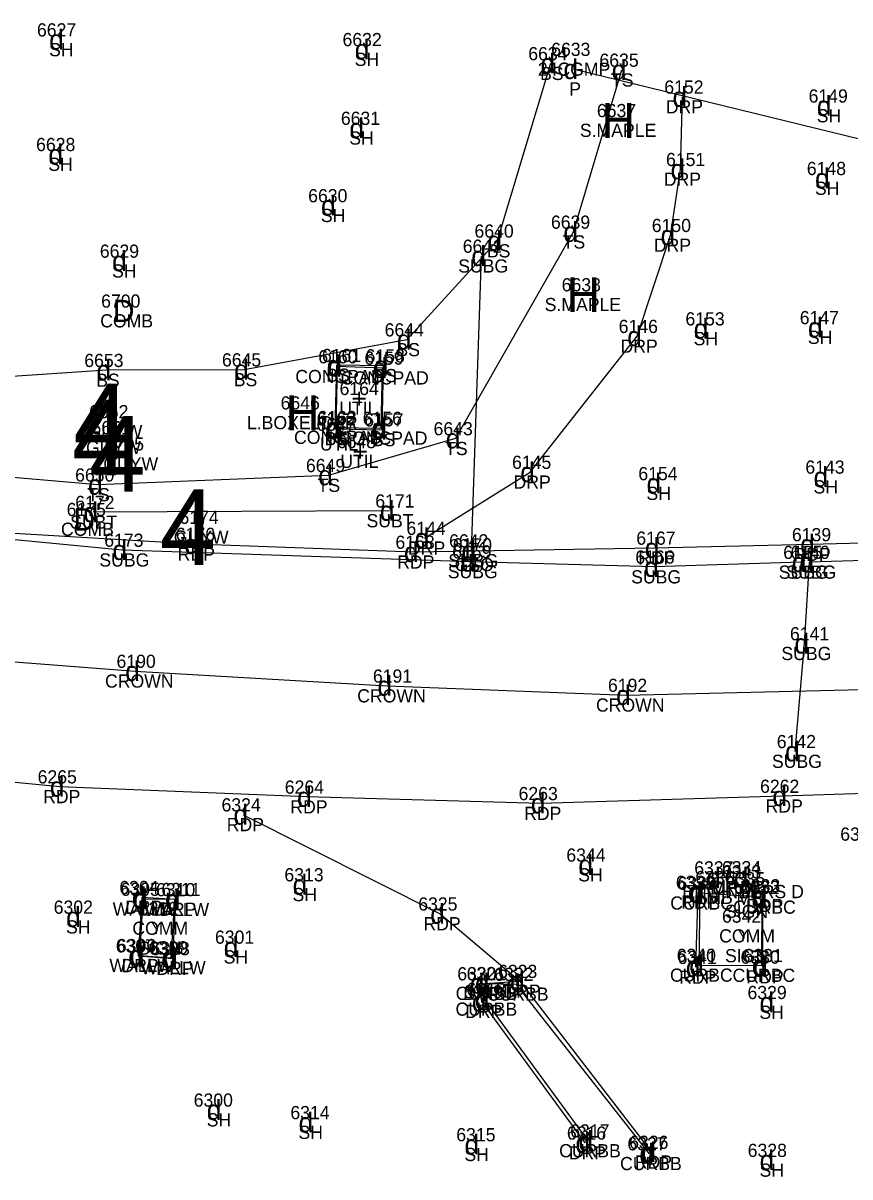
# Model space of a CAD drawing. Extents: x 69415 to 80913, y 7576 to 15059.
# Drawn here: x 75119.5 to 75244.9, y 14346.6 to 14521.7 of the extents above; entities that cross this region are included whole.
import ezdxf

# ---------------------------------------------------------------- set-up
doc = ezdxf.new("R2010")
doc.units = 0
for name, color, linetype in [('Level 11', 7, 'Continuous'), ('Level 12', 7, 'Continuous'), ('Level 14', 7, 'Continuous'), ('Level 15', 7, 'Continuous'), ('Level 43', 7, 'Continuous'), ('Level 46', 7, 'Continuous'), ('Level 47', 7, 'Continuous'), ('Level 48', 7, 'Continuous'), ('Level 59', 7, 'Continuous')]:
    doc.layers.add(name, color=color, linetype=linetype)

msp = doc.modelspace()

# ---------------------------------------------------------------- linework, layer by layer
at = {"layer": 'Level 11'}
for p, q in [((75219.21, 14499.48), (75219.51, 14510.47)), ((75217.7, 14489.47), (75219.21, 14499.48)), ((75212.64, 14474.15), (75217.7, 14489.47)), ((75196.41, 14453.54), (75212.64, 14474.15)), ((75180.39, 14443.53), (75196.41, 14453.54)), ((75145.45, 14442.61), (75114.29, 14444.48)), ((75285.14, 14443.84), (75238.88, 14442.56)), ((75178.76, 14441.41), (75145.45, 14442.61)), ((75215.3, 14442.03), (75178.76, 14441.41)), ((75238.88, 14442.56), (75215.3, 14442.03)), ((75125.04, 14405.82), (75089.24, 14409.2)), ((75162.54, 14404.26), (75125.04, 14405.82)), ((75273.17, 14405.59), (75234.65, 14404.39)), ((75198.01, 14403.28), (75162.54, 14404.26)), ((75234.65, 14404.39), (75198.01, 14403.28)), ((75152.89, 14401.57), (75182.75, 14386.53)), ((75224.62, 14392.01), (75221.83, 14389.82)), ((75228.82, 14392.04), (75224.62, 14392.01)), ((75231.7, 14389.29), (75228.82, 14392.04)), ((75221.83, 14389.82), (75221.52, 14378.43)), ((75222.09, 14389.68), (75222.05, 14378.74)), ((75231.63, 14389.05), (75222.09, 14389.68)), ((75231.73, 14378.47), (75231.7, 14389.29)), ((75137.48, 14389.03), (75136.93, 14380.18)), ((75142.64, 14388.73), (75137.48, 14389.03)), ((75142.21, 14379.76), (75142.64, 14388.73)), ((75231.54, 14378.71), (75231.63, 14389.05)), ((75182.75, 14386.53), (75194.86, 14376.3)), ((75136.93, 14380.18), (75142.21, 14379.76)), ((75222.05, 14378.74), (75231.54, 14378.71)), ((75188.75, 14375.94), (75194.86, 14376.3)), ((75189.07, 14373.23), (75188.75, 14375.94)), ((75189.51, 14373.58), (75189.52, 14375.97)), ((75189.52, 14375.97), (75194.26, 14375.86)), ((75194.26, 14375.86), (75214.47, 14350.15)), ((75194.86, 14376.3), (75214.81, 14350.38)), ((75205.23, 14352.1), (75189.51, 14373.58)), ((75204.78, 14351.78), (75189.07, 14373.23))]:
    msp.add_line(p, q, dxfattribs=at)
at = {"layer": 'Level 12'}
for p, q in [((75167.15, 14469.55), (75166.94, 14460.33)), ((75174.02, 14469.34), (75167.15, 14469.55)), ((75173.81, 14460.21), (75174.02, 14469.34)), ((75166.94, 14460.33), (75173.81, 14460.21)), ((75137.66, 14388.76), (75137.15, 14380.22)), ((75142.49, 14388.7), (75137.66, 14388.76)), ((75141.96, 14379.88), (75142.49, 14388.7)), ((75137.15, 14380.22), (75141.96, 14379.88))]:
    msp.add_line(p, q, dxfattribs=at)
at = {"layer": 'Level 15'}
for p, q in [((75188.98, 14486.32), (75187.48, 14441.62)), ((75175.1, 14447.67), (75130.14, 14447.45)), ((75134.54, 14441.72), (75093.04, 14445.68)), ((75187.39, 14439.95), (75134.54, 14441.72)), ((75215.21, 14439.16), (75187.39, 14439.95)), ((75237.59, 14439.87), (75215.21, 14439.16)), ((75238.75, 14439.88), (75238, 14427.53)), ((75261.83, 14440.59), (75238.75, 14439.88)), ((75238, 14427.53), (75236.58, 14411.17))]:
    msp.add_line(p, q, dxfattribs=at)
at = {"layer": 'Level 48'}
for p, q in [((75199.48, 14515.53), (75191.41, 14488.62)), ((75210.28, 14514.54), (75202.94, 14489.97)), ((75202.94, 14489.97), (75185.11, 14458.63)), ((75191.41, 14488.62), (75177.69, 14473.63)), ((75177.69, 14473.63), (75153.01, 14469.08)), ((75167.04, 14469.75), (75166.8, 14460.13)), ((75174.19, 14469.69), (75167.04, 14469.75)), ((75173.98, 14459.98), (75174.19, 14469.69)), ((75132.13, 14468.99), (75099.03, 14466.77)), ((75153.01, 14469.08), (75132.13, 14468.99)), ((75166.8, 14460.13), (75173.98, 14459.98)), ((75185.11, 14458.63), (75165.76, 14453.05)), ((75130.83, 14451.62), (75097.33, 14454.51)), ((75165.76, 14453.05), (75130.83, 14451.62)), ((75098.58, 14426.29), (75136.48, 14423.35)), ((75136.48, 14423.35), (75174.74, 14421.11)), ((75174.74, 14421.11), (75210.96, 14419.71)), ((75210.96, 14419.71), (75250.32, 14420.68))]:
    msp.add_line(p, q, dxfattribs=at)
at = {"layer": 'Level 59'}
msp.add_line((75270.79, 14498.1), (75202.96, 14514.68), dxfattribs=at)

# ---------------------------------------------------------------- texts
at = {"layer": 'Level 12'}
for p in [(75223.73, 14389.43), (75228.31, 14389.27)]:
    msp.add_text('M', height=2.2, dxfattribs=at).set_placement(p)
at = {"layer": 'Level 14'}
for p in [(75207.25, 14504.25), (75201.91, 14477.82), (75159.32, 14459.9)]:
    msp.add_text('H', height=5.3, dxfattribs=at).set_placement(p)
at = {"layer": 'Level 15'}
for s, height, p in [('D', 3.4, (75133.1, 14476.3)), ('4', 11.5, (75127.12, 14455.47)), ('4', 11.5, (75126.9, 14453.04)), ('4', 11.5, (75129.51, 14450.56)), ('4', 11.5, (75140.2, 14439.44)), ('D', 3.4, (75127.14, 14444.68)), ('I', 1.7, (75186.65, 14440.17))]:
    msp.add_text(s, height=height, dxfattribs=at).set_placement(p)
at = {"layer": 'Level 43'}
for p in [(75227.98, 14389.06), (75138.94, 14383.5), (75227.97, 14382.34)]:
    msp.add_text('Y', height=1.7, dxfattribs=at).set_placement(p)
at = {"layer": 'Level 46'}
for s, p in [('6627', (75121.59, 14519.64)), ('SH', (75123.43, 14516.64)), ('6632', (75167.95, 14518.17)), ('6633', (75199.6, 14516.68)), ('SH', (75169.79, 14515.17)), ('6634', (75196.13, 14516.03)), ('6635', (75206.93, 14515.04)), ('24CGMP', (75197.58, 14513.68)), ('BS', (75197.92, 14513.03)), ('TS', (75208.69, 14512.04)), ('P', (75202.34, 14510.68)), ('6152', (75216.77, 14510.97)), ('6149', (75238.66, 14509.61)), ('DRP', (75217, 14507.97)), ('6631', (75167.7, 14506.23)), ('6637', (75206.54, 14507.4)), ('SH', (75239.89, 14506.61)), ('S.MAPLE', (75203.96, 14504.4)), ('SH', (75168.97, 14503.23)), ('6628', (75121.46, 14502.25)), ('SH', (75123.31, 14499.25)), ('6151', (75217.03, 14499.98)), ('6148', (75238.39, 14498.61)), ('DRP', (75216.7, 14496.98)), ('SH', (75239.62, 14495.61)), ('6630', (75162.74, 14494.48)), ('SH', (75164.67, 14491.48)), ('6639', (75199.57, 14490.47)), ('6640', (75187.97, 14489.12)), ('6150', (75214.87, 14489.97)), ('6641', (75186.19, 14486.82)), ('TS', (75201.35, 14487.47)), ('DRP', (75215.19, 14486.97)), ('6629', (75131.13, 14486.07)), ('BS', (75189.85, 14486.12)), ('SUBG', (75185.5, 14483.82)), ('SH', (75132.98, 14483.07)), ('6638', (75201.2, 14480.97)), ('6700', (75131.33, 14478.5)), ('S.MAPLE', (75198.62, 14477.97)), ('COMB', (75131.19, 14475.5)), ('6146', (75209.85, 14474.65)), ('6153', (75219.98, 14475.8)), ('6147', (75237.32, 14475.99)), ('6644', (75174.34, 14474.13)), ('SH', (75238.55, 14472.99)), ('BS', (75176.13, 14471.13)), ('DRP', (75210.13, 14471.65)), ('SH', (75221.21, 14472.8)), ('6653', (75128.77, 14469.49)), ('6645', (75149.66, 14469.58)), ('6160', (75164.27, 14470.05)), ('6161', (75164.82, 14470.25)), ('6159', (75171.27, 14469.84)), ('6158', (75171.45, 14470.19)), ('BS', (75130.57, 14466.49)), ('BS', (75151.45, 14466.58)), ('CONCPAD', (75160.79, 14467.05)), ('BS', (75165.48, 14467.25)), ('CONCPAD', (75167.66, 14466.84)), ('BS', (75172.63, 14467.19)), ('6164', (75167.5, 14465.24)), ('6646', (75158.56, 14463.05)), ('6652', (75129.51, 14461.72)), ('6162', (75164.02, 14460.63)), ('6163', (75164.15, 14460.83)), ('UTIL', (75167.45, 14462.24)), ('6156', (75171.01, 14460.71)), ('6651', (75129.86, 14459.29)), ('L.BOXELDER', (75153.45, 14460.05)), ('6647', (75164, 14459.82)), ('6157', (75171.24, 14460.48)), ('6643', (75181.76, 14459.13)), ('GUYW', (75129.26, 14458.72)), ('CONCPAD', (75160.59, 14457.83)), ('BS', (75165.24, 14457.63)), ('6648', (75167.09, 14457.18)), ('CONCPAD', (75167.46, 14457.71)), ('BS', (75172.42, 14457.48)), ('GUYW', (75129.04, 14456.29)), ('6705', (75131.88, 14456.81)), ('UTIL', (75164.52, 14456.82)), ('TS', (75183.52, 14456.13)), ('GUYW', (75131.66, 14453.81)), ('UTIL', (75167.61, 14454.18)), ('6145', (75193.67, 14454.04)), ('6650', (75127.38, 14452.12)), ('6649', (75162.4, 14453.55)), ('6154', (75212.83, 14452.32)), ('6143', (75238.17, 14453.31)), ('TS', (75164.17, 14450.55)), ('DRP', (75193.9, 14451.04)), ('SH', (75239.4, 14450.31)), ('TS', (75129.24, 14449.12)), ('SH', (75214.06, 14449.32)), ('6175', (75126.1, 14446.88)), ('6172', (75127.4, 14447.95)), ('6171', (75172.92, 14448.17)), ('SUBT', (75126.63, 14444.95)), ('6174', (75143.21, 14445.69)), ('SUBT', (75171.59, 14445.17)), ('COMB', (75125.23, 14443.88)), ('6176', (75142.66, 14443.11)), ('6144', (75177.65, 14444.03)), ('6139', (75236.13, 14443.06)), ('6173', (75131.8, 14442.22)), ('GUYW', (75142.35, 14442.69)), ('6168', (75175.98, 14441.91)), ('6642', (75184.12, 14442.12)), ('6170', (75184.68, 14441.52)), ('6167', (75212.52, 14442.53)), ('RDP', (75142.94, 14440.11)), ('DRP', (75177.88, 14441.03)), ('6169', (75184.59, 14440.45)), ('6166', (75212.37, 14439.66)), ('6165', (75234.81, 14440.37)), ('6140', (75235.92, 14440.38)), ('RDP', (75236.37, 14440.06)), ('SUBG', (75131.06, 14439.22)), ('RDP', (75176.25, 14438.91)), ('SUBG', (75184, 14439.12)), ('GSO', (75184.96, 14438.52)), ('RDP', (75212.79, 14439.53)), ('SUBG', (75183.92, 14437.45)), ('SUBG', (75211.74, 14436.66)), ('SUBG', (75234.12, 14437.37)), ('SUBG', (75235.28, 14437.38)), ('6141', (75235.83, 14428.03)), ('6190', (75133.66, 14423.85)), ('SUBG', (75234.53, 14425.03)), ('CROWN', (75131.92, 14420.85)), ('6191', (75172.56, 14421.61)), ('CROWN', (75170.18, 14418.61)), ('6192', (75208.22, 14420.21)), ('CROWN', (75206.4, 14417.21)), ('6142', (75233.83, 14411.67)), ('SUBG', (75233.1, 14408.67)), ('6265', (75121.69, 14406.32)), ('6264', (75159.19, 14404.76)), ('6262', (75231.3, 14404.89)), ('RDP', (75122.53, 14403.32)), ('6263', (75194.66, 14403.78)), ('6324', (75149.59, 14402.07)), ('RDP', (75160.03, 14401.76)), ('RDP', (75232.14, 14401.89)), ('RDP', (75195.5, 14400.78)), ('RDP', (75150.38, 14399.07)), ('6345', (75243.46, 14397.63)), ('6344', (75201.91, 14394.45)), ('6337', (75221.31, 14392.51)), ('6334', (75225.51, 14392.54)), ('6313', (75159.13, 14391.46)), ('SH', (75203.71, 14391.45)), ('6336', (75221.47, 14391.03)), ('6343', (75225.52, 14391.91)), ('6335', (75226.11, 14390.87)), ('6304', (75134.09, 14389.53)), ('6305', (75134.28, 14389.26)), ('6310', (75139.66, 14389.2)), ('6311', (75140.47, 14389.23)), ('6338', (75218.52, 14390.32)), ('6339', (75218.77, 14390.18)), ('ENGINEERS D', (75219.51, 14388.91)), ('RDP', (75222.11, 14389.51)), ('RDP', (75226.3, 14389.54)), ('6332', (75228.32, 14389.55)), ('6333', (75228.4, 14389.79)), ('SH', (75160.36, 14388.46)), ('CURBC', (75217.67, 14387.18)), ('RDP', (75219.32, 14387.32)), ('MB', (75223.14, 14388.03)), ('MB', (75227.72, 14387.87)), ('6302', (75124.13, 14386.55)), ('WALLW', (75133.08, 14386.26)), ('DRP', (75134.97, 14386.53)), ('6312', (75137.05, 14386.35)), ('WALLW', (75137.91, 14386.2)), ('DRP', (75140.13, 14386.23)), ('6325', (75179.44, 14387.03)), ('SIGN', (75225.99, 14385.91)), ('CURBC', (75227.21, 14386.55)), ('RDP', (75229.19, 14386.79)), ('SH', (75126, 14383.55)), ('RDP', (75180.23, 14384.03)), ('6342', (75225.52, 14385.19)), ('COMM', (75136.06, 14383.35)), ('6301', (75148.6, 14382)), ('COMM', (75225.09, 14382.19)), ('6307', (75133.55, 14380.68)), ('6306', (75133.71, 14380.72)), ('SIGN', (75136.95, 14380.35)), ('6309', (75138.57, 14380.38)), ('6308', (75138.82, 14380.26)), ('SH', (75149.91, 14379)), ('6340', (75218.65, 14379.24)), ('6341', (75218.78, 14378.93)), ('SIGN', (75225.98, 14379.19)), ('6330', (75228.33, 14378.97)), ('6331', (75228.8, 14379.21)), ('WALLW', (75132.57, 14377.72)), ('DRP', (75134.42, 14377.68)), ('WALLW', (75137.38, 14377.38)), ('DRP', (75139.7, 14377.26)), ('6323', (75191.55, 14376.8)), ('6320', (75185.36, 14376.44)), ('6321', (75186.78, 14376.47)), ('6322', (75190.96, 14376.36)), ('CURBC', (75217.63, 14376.24)), ('RDP', (75219.01, 14375.93)), ('CURBC', (75227.12, 14376.21)), ('RDP', (75229.22, 14375.97)), ('CURBB', (75185.11, 14373.47)), ('6319', (75186.32, 14373.73)), ('DRP', (75186.24, 14373.44)), ('6318', (75186.77, 14374.08)), ('CURBB', (75189.85, 14373.36)), ('DRP', (75192.35, 14373.8)), ('6329', (75229.39, 14373.6)), ('CURBB', (75185.09, 14371.08)), ('DRP', (75186.56, 14370.73)), ('SH', (75231.19, 14370.6)), ('6300', (75145.37, 14357.28)), ('SH', (75147.34, 14354.28)), ('6314', (75160.04, 14355.38)), ('SH', (75161.26, 14352.38)), ('6315', (75185.21, 14352.03)), ('6316', (75201.99, 14352.28)), ('6317', (75202.49, 14352.6)), ('6327', (75211.17, 14350.65)), ('6326', (75211.44, 14350.88)), ('SH', (75186.44, 14349.03)), ('CURBB', (75200.81, 14349.6)), ('DRP', (75202.27, 14349.28)), ('6328', (75229.42, 14349.65)), ('CURBB', (75210.06, 14347.65)), ('RDP', (75212.29, 14347.88)), ('SH', (75231.21, 14346.65))]:
    msp.add_text(s, height=2, dxfattribs=at).set_placement(p)
at = {"layer": 'Level 47'}
for s, p in [('d', (75123.44, 14517.64)), ('d', (75169.8, 14516.17)), ('d', (75197.98, 14514.03)), ('d', (75201.46, 14513.18)), ('d', (75208.78, 14513.04)), ('d', (75218.01, 14508.97)), ('d', (75239.91, 14507.61)), ('d', (75168.99, 14504.23)), ('d', (75123.32, 14500.25)), ('d', (75217.71, 14497.98)), ('d', (75239.63, 14496.61)), ('d', (75164.68, 14492.48)), ('d', (75201.44, 14488.47)), ('d', (75216.2, 14487.97)), ('d', (75189.91, 14487.12)), ('d', (75132.99, 14484.07)), ('d', (75187.48, 14484.82)), ('d', (75221.22, 14473.8)), ('d', (75238.56, 14473.99)), ('d', (75176.19, 14472.13)), ('d', (75211.14, 14472.65)), ('d', (75165.54, 14468.25)), ('d', (75172.69, 14468.19)), ('d', (75130.63, 14467.49)), ('d', (75151.51, 14467.58)), ('d', (75165.65, 14468.05)), ('d', (75172.52, 14467.84)), ('+', (75169.31, 14463.24)), ('d', (75165.3, 14458.63)), ('d', (75165.44, 14458.83)), ('d', (75172.31, 14458.71)), ('d', (75172.48, 14458.48)), ('+', (75166.38, 14457.82)), ('d', (75183.61, 14457.13)), ('+', (75169.46, 14455.18)), ('d', (75164.26, 14451.55)), ('d', (75194.91, 14452.04)), ('d', (75239.41, 14451.31)), ('d', (75129.33, 14450.12)), ('d', (75214.07, 14450.32)), ('d', (75128.64, 14445.95)), ('d', (75173.6, 14446.17)), ('d', (75178.89, 14442.03)), ('d', (75133.04, 14440.22)), ('d', (75143.95, 14441.11)), ('d', (75213.8, 14440.53)), ('d', (75237.38, 14441.06)), ('d', (75177.26, 14439.91)), ('d', (75185.89, 14438.45)), ('d', (75185.98, 14440.12)), ('d', (75213.71, 14437.66)), ('d', (75236.09, 14438.37)), ('d', (75237.25, 14438.38)), ('d', (75236.5, 14426.03)), ('d', (75134.98, 14421.85)), ('d', (75173.24, 14419.61)), ('d', (75209.46, 14418.21)), ('d', (75235.08, 14409.67)), ('d', (75123.54, 14404.32)), ('d', (75161.04, 14402.76)), ('d', (75196.51, 14401.78)), ('d', (75233.15, 14402.89)), ('d', (75151.39, 14400.07)), ('d', (75203.72, 14392.45)), ('d', (75160.37, 14389.46)), ('d', (75223.12, 14390.51)), ('d', (75227.32, 14390.54)), ('d', (75220.33, 14388.32)), ('d', (75220.59, 14388.18)), ('d', (75230.2, 14387.79)), ('d', (75135.98, 14387.53)), ('d', (75136.16, 14387.26)), ('d', (75140.99, 14387.2)), ('d', (75141.14, 14387.23)), ('d', (75230.13, 14387.55)), ('d', (75126.01, 14384.55)), ('d', (75181.25, 14385.03)), ('d', (75149.92, 14380)), ('d', (75135.43, 14378.68)), ('d', (75135.65, 14378.72)), ('d', (75140.46, 14378.38)), ('d', (75140.71, 14378.26)), ('d', (75220.55, 14377.24)), ('d', (75230.04, 14377.21)), ('d', (75220.02, 14376.93)), ('d', (75230.23, 14376.97)), ('d', (75187.25, 14374.44)), ('d', (75188.02, 14374.47)), ('d', (75192.76, 14374.36)), ('d', (75193.36, 14374.8)), ('d', (75188.01, 14372.08)), ('d', (75187.57, 14371.73)), ('d', (75231.21, 14371.6)), ('d', (75147.35, 14355.28)), ('d', (75161.28, 14353.38)), ('d', (75186.45, 14350.03)), ('d', (75203.28, 14350.28)), ('d', (75203.73, 14350.6)), ('d', (75212.97, 14348.65)), ('d', (75213.31, 14348.88)), ('d', (75231.22, 14347.65))]:
    msp.add_text(s, height=3, dxfattribs=at).set_placement(p)

doc.saveas('drawing.dxf')
